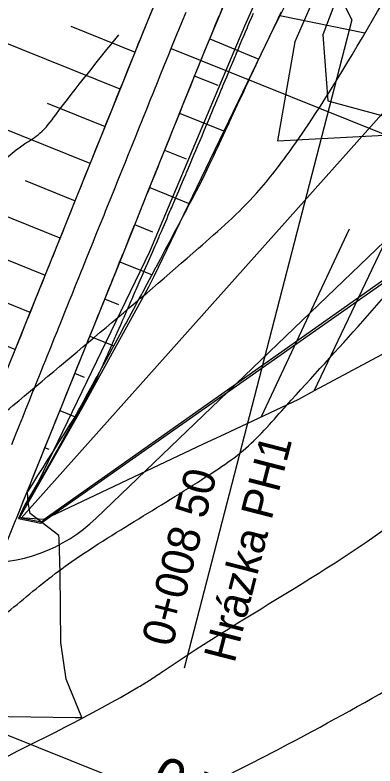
# Model space of a CAD drawing. Extents: x -564043 to -563833, y -1163561 to -1163412.
# Drawn here: x -563977.47 to -563966.25, y -1163509.03 to -1163485.61 of the extents above; entities that cross this region are included whole.
import ezdxf

# ---------------------------------------------------------------- set-up
doc = ezdxf.new("R2010")
doc.units = 0
for name, color, linetype in [('5', 7, 'Continuous'), ('_popis staničení PH1', 7, 'Continuous'), ('_popis staničení T1', 7, 'Continuous'), ('Default', 7, 'Continuous'), ('Line', 7, 'Continuous'), ('Vrstva 24', 7, 'Continuous'), ('Vrstva 25', 7, 'Continuous'), ('Vrstva 26', 7, 'Continuous')]:
    doc.layers.add(name, color=color, linetype=linetype)

msp = doc.modelspace()

# ---------------------------------------------------------------- linework, layer by layer
for points in [[(-563976.663, -1163501.462), (-563964.742, -1163493.091), (-563961.829, -1163491.15), (-563957.41, -1163486.988), (-563956.735, -1163486.627), (-563953.281, -1163481.221), (-563953.993, -1163478.343), (-563957.796, -1163470.824), (-563957.81, -1163470.439), (-563957.835, -1163469.754), (-563958.239, -1163469.063), (-563958.187, -1163468.683), (-563959.529, -1163466.077), (-563960.166, -1163464.984), (-563964.31, -1163473.527), (-563966.903, -1163478.544), (-563968.406, -1163481.669), (-563970.316, -1163485.955), (-563973.278, -1163492.988), (-563976.735, -1163500.155), (-563977.161, -1163500.889), (-563977.363, -1163501.307)], [(-563962.125, -1163475.875), (-563962.765, -1163475.108), (-563963.856, -1163475.351), (-563965.212, -1163477.785), (-563966.919, -1163483.486), (-563967.557, -1163485.407), (-563967.871, -1163486.226), (-563967.716, -1163488.285), (-563965.306, -1163488.933), (-563963.594, -1163489.868), (-563962.736, -1163489.387), (-563960.869, -1163487.453), (-563959.333, -1163482.497), (-563959.613, -1163479.666)]]:
    msp.add_lwpolyline(points, close=True)
for points in [[(-563968.084, -1163484.934), (-563968.744, -1163486.445), (-563969.289, -1163489.534), (-563965.164, -1163489.309), (-563965.164, -1163489.309), (-563964.25, -1163489.835), (-563963.508, -1163490.263), (-563963.061, -1163489.994), (-563962.883, -1163489.889), (-563962.657, -1163489.751), (-563960.727, -1163487.738), (-563960.348, -1163486.241), (-563960.31, -1163486.212), (-563960.154, -1163486.129), (-563958.95, -1163482.892)], [(-563951.913, -1163488.197), (-563954.263, -1163490.192), (-563956.079, -1163491.487), (-563957.379, -1163492.414), (-563960.591, -1163493.664), (-563961.319, -1163493.948), (-563961.866, -1163494.161), (-563963.182, -1163494.674), (-563968.138, -1163497.33), (-563968.634, -1163497.596), (-563970.944, -1163498.688), (-563971.597, -1163498.997), (-563976.56, -1163501.343), (-563977.332, -1163501.295), (-563976.988, -1163500.693), (-563975.559, -1163498.192), (-563975.396, -1163497.906), (-563973.296, -1163494.084), (-563973.133, -1163493.747), (-563971.654, -1163490.682), (-563969.513, -1163486.248), (-563968.702, -1163484.611)], [(-563977.812, -1163496.922), (-563977.438, -1163495.994), (-563977.065, -1163495.066), (-563976.691, -1163494.139), (-563976.318, -1163493.211), (-563975.945, -1163492.283), (-563975.571, -1163491.355), (-563975.198, -1163490.428), (-563974.825, -1163489.5), (-563974.451, -1163488.572), (-563974.078, -1163487.645), (-563973.705, -1163486.717), (-563973.527, -1163486.276), (-563973.328, -1163485.785), (-563972.941, -1163484.852)], [(-563977.421, -1163501.309), (-563977.076, -1163500.451), (-563977.017, -1163500.304), (-563976.703, -1163499.524), (-563976.33, -1163498.596), (-563975.956, -1163497.668), (-563975.583, -1163496.741), (-563975.209, -1163495.813), (-563974.836, -1163494.885), (-563974.463, -1163493.958), (-563974.089, -1163493.03), (-563973.716, -1163492.102), (-563973.343, -1163491.175), (-563972.969, -1163490.247), (-563972.596, -1163489.319), (-563972.223, -1163488.391), (-563971.849, -1163487.464), (-563971.672, -1163487.023), (-563971.476, -1163486.542), (-563971.097, -1163485.627), (-563970.817, -1163484.966)], [(-563977.823, -1163502.307), (-563977.45, -1163501.379), (-563977.421, -1163501.309), (-563977.309, -1163501.03), (-563977.309, -1163501.029), (-563977.198, -1163500.753), (-563977.087, -1163500.478), (-563977.076, -1163500.451), (-563976.976, -1163500.203), (-563976.865, -1163499.927), (-563976.755, -1163499.652), (-563976.703, -1163499.524), (-563976.644, -1163499.377), (-563976.533, -1163499.101), (-563976.422, -1163498.826), (-563976.33, -1163498.596), (-563976.311, -1163498.551), (-563976.201, -1163498.275), (-563976.09, -1163498), (-563975.979, -1163497.725), (-563975.956, -1163497.668), (-563975.868, -1163497.449), (-563975.757, -1163497.174), (-563975.646, -1163496.899), (-563975.583, -1163496.741), (-563975.536, -1163496.623), (-563975.425, -1163496.348), (-563975.314, -1163496.073), (-563975.209, -1163495.813), (-563975.203, -1163495.797), (-563975.092, -1163495.522), (-563974.982, -1163495.247), (-563974.871, -1163494.971), (-563974.836, -1163494.885), (-563974.76, -1163494.696), (-563974.649, -1163494.421), (-563974.538, -1163494.145), (-563974.463, -1163493.958), (-563974.428, -1163493.87), (-563974.317, -1163493.595), (-563974.206, -1163493.319), (-563974.095, -1163493.044), (-563974.089, -1163493.03), (-563973.984, -1163492.769), (-563973.873, -1163492.493), (-563973.763, -1163492.218), (-563973.716, -1163492.102), (-563973.652, -1163491.943), (-563973.541, -1163491.668), (-563973.43, -1163491.392), (-563973.343, -1163491.175), (-563973.319, -1163491.117), (-563973.209, -1163490.842), (-563973.098, -1163490.566), (-563972.987, -1163490.291), (-563972.969, -1163490.247), (-563972.876, -1163490.016), (-563972.765, -1163489.74), (-563972.655, -1163489.465), (-563972.596, -1163489.319), (-563972.544, -1163489.19), (-563972.433, -1163488.914), (-563972.322, -1163488.639), (-563972.223, -1163488.391), (-563972.211, -1163488.364), (-563972.101, -1163488.088), (-563971.99, -1163487.813), (-563971.879, -1163487.538), (-563971.849, -1163487.464), (-563971.768, -1163487.262), (-563971.672, -1163487.023), (-563971.657, -1163486.987), (-563971.547, -1163486.715), (-563971.476, -1163486.542), (-563971.436, -1163486.443), (-563971.324, -1163486.171), (-563971.212, -1163485.9), (-563971.098, -1163485.629), (-563971.097, -1163485.627), (-563970.984, -1163485.358)], [(-563977.571, -1163499.003), (-563977.461, -1163498.728), (-563977.35, -1163498.453), (-563977.257, -1163498.223), (-563977.239, -1163498.177), (-563977.128, -1163497.902), (-563977.017, -1163497.627), (-563976.907, -1163497.351), (-563976.884, -1163497.295), (-563976.796, -1163497.076), (-563976.685, -1163496.801), (-563976.574, -1163496.525), (-563976.511, -1163496.367), (-563976.463, -1163496.25), (-563976.353, -1163495.975), (-563976.242, -1163495.699), (-563976.137, -1163495.44), (-563976.131, -1163495.424), (-563976.02, -1163495.149), (-563975.909, -1163494.873), (-563975.798, -1163494.598), (-563975.764, -1163494.512), (-563975.688, -1163494.323), (-563975.577, -1163494.047), (-563975.466, -1163493.772), (-563975.39, -1163493.584), (-563975.355, -1163493.497), (-563975.244, -1163493.221), (-563975.134, -1163492.946), (-563975.023, -1163492.671), (-563975.017, -1163492.657), (-563974.912, -1163492.395), (-563974.801, -1163492.12), (-563974.69, -1163491.845), (-563974.644, -1163491.729), (-563974.58, -1163491.569), (-563974.469, -1163491.294), (-563974.358, -1163491.019), (-563974.27, -1163490.801), (-563974.247, -1163490.744), (-563974.136, -1163490.468), (-563974.025, -1163490.193), (-563973.915, -1163489.918), (-563973.897, -1163489.873), (-563973.804, -1163489.642), (-563973.693, -1163489.367), (-563973.582, -1163489.092), (-563973.524, -1163488.946), (-563973.471, -1163488.816), (-563973.361, -1163488.541), (-563973.25, -1163488.266), (-563973.15, -1163488.018), (-563973.139, -1163487.99), (-563973.028, -1163487.715), (-563972.917, -1163487.44), (-563972.807, -1163487.164), (-563972.777, -1163487.09), (-563972.696, -1163486.889), (-563972.599, -1163486.649), (-563972.585, -1163486.614), (-563972.474, -1163486.339), (-563972.402, -1163486.163), (-563972.361, -1163486.064), (-563972.249, -1163485.789), (-563972.135, -1163485.515)], [(-563977.502, -1163496.152), (-563977.438, -1163495.994), (-563977.391, -1163495.877), (-563977.28, -1163495.601), (-563977.169, -1163495.326), (-563977.065, -1163495.066), (-563977.059, -1163495.051), (-563976.948, -1163494.775), (-563976.837, -1163494.5), (-563976.726, -1163494.225), (-563976.691, -1163494.139), (-563976.615, -1163493.949), (-563976.505, -1163493.674), (-563976.394, -1163493.399), (-563976.318, -1163493.211), (-563976.283, -1163493.123), (-563976.172, -1163492.848), (-563976.061, -1163492.573), (-563975.95, -1163492.297), (-563975.945, -1163492.283), (-563975.84, -1163492.022), (-563975.729, -1163491.747), (-563975.618, -1163491.471), (-563975.571, -1163491.355), (-563975.507, -1163491.196), (-563975.396, -1163490.921), (-563975.286, -1163490.645), (-563975.198, -1163490.428), (-563975.175, -1163490.37), (-563975.064, -1163490.095), (-563974.953, -1163489.819), (-563974.842, -1163489.544), (-563974.825, -1163489.5), (-563974.732, -1163489.269), (-563974.621, -1163488.994), (-563974.51, -1163488.718), (-563974.451, -1163488.572), (-563974.399, -1163488.443), (-563974.288, -1163488.168), (-563974.177, -1163487.892), (-563974.078, -1163487.645), (-563974.067, -1163487.617), (-563973.956, -1163487.342), (-563973.845, -1163487.066), (-563973.734, -1163486.791), (-563973.705, -1163486.717), (-563973.623, -1163486.516), (-563973.527, -1163486.276), (-563973.512, -1163486.24), (-563973.4, -1163485.962), (-563973.328, -1163485.785), (-563973.287, -1163485.685), (-563973.173, -1163485.407)], [(-563977.077, -1163500.482), (-563977.061, -1163500.458), (-563976.914, -1163500.227), (-563976.753, -1163499.973), (-563976.591, -1163499.718), (-563976.516, -1163499.599), (-563976.429, -1163499.463), (-563976.268, -1163499.208), (-563976.107, -1163498.953), (-563975.973, -1163498.74), (-563975.946, -1163498.698), (-563975.785, -1163498.442), (-563975.625, -1163498.187), (-563975.48, -1163497.925), (-563975.451, -1163497.872), (-563975.336, -1163497.663), (-563975.193, -1163497.401), (-563975.049, -1163497.139), (-563974.967, -1163496.989), (-563974.906, -1163496.877), (-563974.763, -1163496.614), (-563974.62, -1163496.352), (-563974.485, -1163496.104), (-563974.477, -1163496.09), (-563974.335, -1163495.827), (-563974.192, -1163495.564), (-563974.05, -1163495.302), (-563974.006, -1163495.219), (-563973.909, -1163495.039), (-563973.767, -1163494.776), (-563973.625, -1163494.513), (-563973.529, -1163494.333), (-563973.484, -1163494.25), (-563973.343, -1163493.987), (-563973.202, -1163493.723), (-563973.062, -1163493.46), (-563973.055, -1163493.446), (-563972.922, -1163493.196), (-563972.782, -1163492.933), (-563972.642, -1163492.669), (-563972.583, -1163492.558), (-563972.502, -1163492.405), (-563972.363, -1163492.142), (-563972.224, -1163491.878), (-563972.114, -1163491.669), (-563972.085, -1163491.614), (-563971.946, -1163491.35), (-563971.808, -1163491.085), (-563971.669, -1163490.821), (-563971.647, -1163490.779), (-563971.537, -1163490.555), (-563971.41, -1163490.286), (-563971.283, -1163490.017), (-563971.216, -1163489.874), (-563971.157, -1163489.748), (-563971.03, -1163489.479), (-563970.904, -1163489.21), (-563970.791, -1163488.968), (-563970.778, -1163488.94), (-563970.653, -1163488.671), (-563970.527, -1163488.402), (-563970.402, -1163488.132), (-563970.368, -1163488.06), (-563970.277, -1163487.863), (-563970.168, -1163487.628), (-563970.152, -1163487.594), (-563970.03, -1163487.332), (-563969.952, -1163487.164), (-563969.908, -1163487.069), (-563969.785, -1163486.808), (-563969.662, -1163486.546), (-563969.538, -1163486.285), (-563969.537, -1163486.283), (-563969.414, -1163486.024), (-563969.289, -1163485.763), (-563969.233, -1163485.646), (-563969.164, -1163485.502)], [(-563977.077, -1163500.482), (-563977.061, -1163500.458), (-563976.914, -1163500.227), (-563976.753, -1163499.973), (-563976.591, -1163499.718), (-563976.516, -1163499.599), (-563976.429, -1163499.463), (-563976.268, -1163499.208), (-563976.107, -1163498.953), (-563975.973, -1163498.74), (-563975.946, -1163498.698), (-563975.785, -1163498.442), (-563975.625, -1163498.187), (-563975.48, -1163497.925), (-563975.451, -1163497.872), (-563975.336, -1163497.663), (-563975.193, -1163497.401), (-563975.049, -1163497.139), (-563974.967, -1163496.989), (-563974.906, -1163496.877), (-563974.763, -1163496.614), (-563974.62, -1163496.352), (-563974.485, -1163496.104), (-563974.477, -1163496.09), (-563974.335, -1163495.827), (-563974.192, -1163495.564), (-563974.05, -1163495.302), (-563974.006, -1163495.219), (-563973.909, -1163495.039), (-563973.767, -1163494.776), (-563973.625, -1163494.513), (-563973.529, -1163494.333), (-563973.484, -1163494.25), (-563973.343, -1163493.987), (-563973.202, -1163493.723), (-563973.062, -1163493.46), (-563973.055, -1163493.446), (-563972.922, -1163493.196), (-563972.782, -1163492.933), (-563972.642, -1163492.669), (-563972.583, -1163492.558), (-563972.502, -1163492.405), (-563972.363, -1163492.142), (-563972.224, -1163491.878), (-563972.114, -1163491.669), (-563972.085, -1163491.614), (-563971.946, -1163491.35), (-563971.808, -1163491.085), (-563971.669, -1163490.821), (-563971.647, -1163490.779), (-563971.537, -1163490.555), (-563971.41, -1163490.286), (-563971.283, -1163490.017), (-563971.216, -1163489.874), (-563971.157, -1163489.748), (-563971.03, -1163489.479), (-563970.904, -1163489.21), (-563970.791, -1163488.968), (-563970.778, -1163488.94), (-563970.653, -1163488.671), (-563970.527, -1163488.402), (-563970.402, -1163488.132), (-563970.368, -1163488.06), (-563970.277, -1163487.863), (-563970.168, -1163487.628), (-563970.152, -1163487.594), (-563970.03, -1163487.332), (-563969.952, -1163487.164), (-563969.908, -1163487.069), (-563969.785, -1163486.808), (-563969.662, -1163486.546), (-563969.538, -1163486.285), (-563969.537, -1163486.283), (-563969.414, -1163486.024), (-563969.289, -1163485.763), (-563969.233, -1163485.646), (-563969.164, -1163485.502)], [(-563979.198, -1163507.467), (-563978.368, -1163507.477), (-563975.597, -1163507.515), (-563975.386, -1163507.517), (-563975.87, -1163506.327), (-563976.036, -1163505.182), (-563976.046, -1163504.1), (-563976.056, -1163503.018), (-563976.088, -1163501.927), (-563976.1, -1163501.84), (-563976.996, -1163501.156), (-563976.997, -1163501.154), (-563977.062, -1163500.808), (-563977.077, -1163500.482)], [(-563979.198, -1163507.467), (-563978.368, -1163507.477), (-563975.597, -1163507.515), (-563975.386, -1163507.517), (-563975.87, -1163506.327), (-563976.036, -1163505.182), (-563976.046, -1163504.1), (-563976.056, -1163503.018), (-563976.088, -1163501.927), (-563976.1, -1163501.84), (-563976.996, -1163501.156), (-563976.997, -1163501.154), (-563977.062, -1163500.808), (-563977.077, -1163500.482)]]:
    msp.add_lwpolyline(points)
at = {"layer": '5'}
msp.add_line((-563974.94, -1163501.303), (-563959.546, -1163486.507), dxfattribs=at)
msp.add_arc((-563978.405, -1163497.698), 5, 218.997, 313.8653, dxfattribs=at)
at = {"layer": '_popis staničení PH1'}
for points in [[(-563972.599, -1163486.649), (-563954.098, -1163494.096)], [(-563980.73, -1163506.85), (-563966.814, -1163512.451)]]:
    msp.add_lwpolyline(points, dxfattribs=at)
at = {"layer": '_popis staničení T1'}
msp.add_lwpolyline([(-563969.764, -1163480.269), (-563966.967, -1163485.757), (-563972.194, -1163505.976)], dxfattribs=at)
at = {"layer": 'Default'}
msp.add_lwpolyline([(-563962.482, -1163491.404), (-563976.56, -1163501.343), (-563976.657, -1163501.429), (-563977.332, -1163501.295), (-563974.976, -1163497.082), (-563974.974, -1163497.079), (-563974.939, -1163497), (-563974.935, -1163496.992), (-563974.849, -1163496.797), (-563974.841, -1163496.78), (-563974.722, -1163496.513), (-563974.711, -1163496.488), (-563974.596, -1163496.229), (-563974.589, -1163496.212), (-563974.532, -1163496.085), (-563974.525, -1163496.068), (-563974.47, -1163495.944), (-563974.453, -1163495.906), (-563974.344, -1163495.659), (-563974.324, -1163495.615), (-563974.218, -1163495.374), (-563974.203, -1163495.339), (-563974.128, -1163495.17), (-563974.122, -1163495.155), (-563974.093, -1163495.09), (-563974.069, -1163495.034), (-563973.968, -1163494.805), (-563973.941, -1163494.744), (-563973.843, -1163494.52), (-563973.816, -1163494.459), (-563973.727, -1163494.254), (-563973.725, -1163494.249), (-563973.718, -1163494.234), (-563973.688, -1163494.165), (-563973.594, -1163493.949), (-563973.562, -1163493.876), (-563973.47, -1163493.664), (-563973.436, -1163493.586), (-563973.346, -1163493.378), (-563973.341, -1163493.366), (-563973.328, -1163493.337), (-563973.297, -1163493.267), (-563973.222, -1163493.093), (-563973.185, -1163493.008), (-563973.099, -1163492.807), (-563973.061, -1163492.719), (-563972.975, -1163492.522), (-563972.961, -1163492.488), (-563972.931, -1163492.418), (-563972.905, -1163492.359), (-563972.852, -1163492.236), (-563972.812, -1163492.141), (-563972.729, -1163491.95), (-563972.688, -1163491.852), (-563972.607, -1163491.664), (-563972.582, -1163491.606), (-563972.536, -1163491.499), (-563972.518, -1163491.456), (-563972.485, -1163491.378), (-563972.441, -1163491.275), (-563972.363, -1163491.092), (-563972.318, -1163490.986), (-563972.241, -1163490.805), (-563972.204, -1163490.719), (-563972.145, -1163490.579), (-563972.135, -1163490.556), (-563972.119, -1163490.519), (-563972.072, -1163490.408), (-563971.998, -1163490.232), (-563971.95, -1163490.12), (-563971.877, -1163489.946), (-563971.829, -1163489.833), (-563971.756, -1163489.659), (-563971.756, -1163489.659), (-563971.755, -1163489.658), (-563971.707, -1163489.544), (-563971.635, -1163489.372), (-563971.587, -1163489.257), (-563971.515, -1163489.086), (-563971.466, -1163488.969), (-563971.395, -1163488.799), (-563971.384, -1163488.773), (-563971.368, -1163488.735), (-563971.33, -1163488.644), (-563971.275, -1163488.512), (-563971.225, -1163488.393), (-563971.155, -1163488.224), (-563971.105, -1163488.105), (-563971.036, -1163487.937), (-563971.014, -1163487.885), (-563970.984, -1163487.812), (-563970.955, -1163487.744), (-563970.916, -1163487.65), (-563970.868, -1163487.533), (-563970.802, -1163487.373), (-563970.8, -1163487.368), (-563970.797, -1163487.363), (-563970.747, -1163487.242), (-563970.68, -1163487.081), (-563970.647, -1163487.002), (-563970.604, -1163486.898), (-563970.586, -1163486.855), (-563970.563, -1163486.799), (-563970.511, -1163486.677), (-563970.445, -1163486.518), (-563970.392, -1163486.395), (-563970.326, -1163486.237), (-563970.28, -1163486.13), (-563970.222, -1163485.995), (-563970.215, -1163485.978), (-563970.206, -1163485.957), (-563970.153, -1163485.832), (-563970.086, -1163485.676), (-563970.032, -1163485.551)], dxfattribs=at)
at = {"layer": 'Line'}
for p, q in [((-563962.901, -1163485.181), (-563977.279, -1163501.298)), ((-563966.564, -1163486.174), (-563969.208, -1163485.632)), ((-563975.726, -1163485.954), (-563973.723, -1163486.764)), ((-563968.138, -1163497.33), (-563962.69, -1163485.858)), ((-563974.19, -1163487.923), (-563977.994, -1163486.392)), ((-563971.398, -1163486.352), (-563969.867, -1163486.983)), ((-563971.129, -1163487.809), (-563971.868, -1163487.51)), ((-563976.466, -1163488.355), (-563974.657, -1163489.083)), ((-563975.123, -1163490.242), (-563978.542, -1163488.867)), ((-563972.335, -1163488.67), (-563970.918, -1163489.24)), ((-563972.126, -1163490.101), (-563972.801, -1163489.829)), ((-563977.155, -1163490.772), (-563975.59, -1163491.402)), ((-563973.268, -1163490.989), (-563972.021, -1163491.491)), ((-563976.057, -1163492.562), (-563978.885, -1163491.423)), ((-563973.171, -1163492.376), (-563973.735, -1163492.149)), ((-563967.053, -1163492.285), (-563969.789, -1163498.142)), ((-563977.783, -1163493.214), (-563976.523, -1163493.721)), ((-563974.201, -1163493.308), (-563973.196, -1163493.713)), ((-563976.99, -1163494.881), (-563979.193, -1163493.994)), ((-563974.23, -1163494.644), (-563974.668, -1163494.468)), ((-563978.396, -1163495.662), (-563977.457, -1163496.04)), ((-563975.135, -1163495.627), (-563974.389, -1163495.928)), ((-563975.296, -1163496.91), (-563975.602, -1163496.787)), ((-563976.068, -1163497.947), (-563975.597, -1163498.136)), ((-563976.403, -1163499.159), (-563976.535, -1163499.106)), ((-563977.002, -1163500.266), (-563976.952, -1163500.286))]:
    msp.add_line(p, q, dxfattribs=at)
at = {"layer": 'Vrstva 24'}
for points in [[(-563987.107, -1163486.915), (-563987.454, -1163489.613), (-563987.517, -1163490.15), (-563987.54, -1163490.422), (-563987.53, -1163490.559), (-563987.493, -1163490.695), (-563987.417, -1163490.784), (-563987.298, -1163490.832), (-563987.065, -1163490.801), (-563986.897, -1163490.636), (-563986.866, -1163490.616), (-563986.653, -1163490.561), (-563986.65, -1163490.24), (-563986.645, -1163490.2), (-563986.382, -1163489.381), (-563986.092, -1163488.576), (-563985.799, -1163487.775), (-563985.528, -1163486.967), (-563985.38, -1163486.476), (-563984.961, -1163484.997), (-563984.678, -1163484.011), (-563984.372, -1163483.032), (-563984.225, -1163482.649), (-563983.962, -1163482.075), (-563983.672, -1163481.512), (-563983.189, -1163480.348), (-563983.119, -1163479.959), (-563982.881, -1163478.598), (-563982.738, -1163477.921), (-563982.65, -1163477.583), (-563982.6, -1163477.415), (-563982.546, -1163477.247), (-563982.332, -1163477.109), (-563982.215, -1163477.074), (-563982.092, -1163477.059), (-563981.971, -1163477.035), (-563981.858, -1163476.974), (-563981.222, -1163476.317), (-563980.763, -1163475.576), (-563980.303, -1163473.933), (-563980.283, -1163473.505), (-563980.299, -1163473.076), (-563980.318, -1163472.648), (-563980.308, -1163472.221), (-563980.208, -1163471.241), (-563979.978, -1163470.27), (-563979.506, -1163469.655), (-563979.053, -1163469.383), (-563978.331, -1163469.068), (-563977.756, -1163469.029), (-563977.053, -1163469.053), (-563976.495, -1163468.977), (-563976.227, -1163468.861), (-563976.095, -1163468.775), (-563975.963, -1163468.666), (-563975.645, -1163468.239), (-563975.569, -1163468.015), (-563975.54, -1163467.788), (-563975.712, -1163467.263), (-563975.92, -1163467.014), (-563976.134, -1163466.799), (-563976.603, -1163466.431), (-563977.767, -1163465.694), (-563978.114, -1163465.416), (-563978.319, -1163465.046), (-563978.354, -1163464.593), (-563978.366, -1163464.139), (-563978.374, -1163463.685), (-563978.396, -1163463.232), (-563978.403, -1163463.165), (-563978.508, -1163462.771), (-563978.665, -1163462.394), (-563979.088, -1163461.691), (-563979.473, -1163461.171), (-563980.119, -1163460.346)], [(-563978.297, -1163509.021), (-563978.261, -1163509.003), (-563973.613, -1163506.565), (-563973.263, -1163506.351), (-563972.852, -1163506.074), (-563964.784, -1163500.778), (-563963.064, -1163499.262), (-563960.133, -1163495.845), (-563958.857, -1163494.133), (-563956.661, -1163490.461), (-563954.703, -1163486.917), (-563951.017, -1163480.396), (-563950.659, -1163479.782), (-563950.563, -1163479.619)], [(-563978.949, -1163516.619), (-563975.171, -1163515.313), (-563974.108, -1163514.884), (-563972.002, -1163513.885), (-563969.907, -1163512.865), (-563967.813, -1163511.846), (-563965.709, -1163510.847), (-563964.325, -1163510.207), (-563962.597, -1163509.381), (-563961.075, -1163508.613), (-563959.57, -1163507.812), (-563958.075, -1163506.99), (-563956.583, -1163506.159), (-563955.558, -1163505.578), (-563954.547, -1163504.976), (-563953.555, -1163504.342), (-563952.588, -1163503.665), (-563951.319, -1163502.66), (-563950.112, -1163501.587), (-563949.038, -1163500.583), (-563947.98, -1163499.563), (-563946.918, -1163498.547), (-563945.835, -1163497.554), (-563945.703, -1163497.443), (-563945.609, -1163497.371), (-563945.171, -1163496.955), (-563943.72, -1163495.5)]]:
    msp.add_spline(points, degree=3, dxfattribs=at)
at = {"layer": 'Vrstva 25'}
msp.add_spline([(-563979.181, -1163499.008), (-563978.428, -1163498.506), (-563977.533, -1163497.79), (-563971.745, -1163492.882), (-563969.933, -1163491.157), (-563968.824, -1163489.747), (-563966.163, -1163485.494), (-563965.399, -1163484.181), (-563964.1, -1163481.868), (-563961.431, -1163477.021), (-563960.731, -1163475.725), (-563960.044, -1163474.189), (-563959.617, -1163472.641), (-563959.116, -1163469.866), (-563959.228, -1163469.046), (-563959.512, -1163468.326), (-563959.82, -1163467.638), (-563960.515, -1163466.313), (-563961.208, -1163465.1)], degree=3, dxfattribs=at)
at = {"layer": 'Vrstva 26'}
for points in [[(-563980.746, -1163506.255), (-563980.047, -1163505.928), (-563978.898, -1163505.186), (-563978.091, -1163504.559), (-563977.304, -1163503.908), (-563976.514, -1163503.264), (-563975.695, -1163502.656), (-563974.591, -1163501.929), (-563973.468, -1163501.232), (-563972.341, -1163500.538), (-563971.226, -1163499.825), (-563970.447, -1163499.268), (-563969.15, -1163497.951), (-563964.517, -1163492.611), (-563963.2, -1163490.7), (-563960.284, -1163485.41), (-563958.779, -1163482.786), (-563956.142, -1163478.307), (-563954.428, -1163475.228)], [(-564001.195, -1163498.271), (-563999.625, -1163497.54), (-563999.32, -1163497.49), (-563999.014, -1163497.455), (-563998.404, -1163497.374), (-563997.456, -1163497.19), (-563996.983, -1163497.106), (-563996.746, -1163497.08), (-563996.628, -1163497.073), (-563996.51, -1163497.07), (-563996.001, -1163497.405), (-563995.843, -1163497.69), (-563995.811, -1163497.929), (-563995.865, -1163498.008), (-563995.966, -1163498.084), (-563996.177, -1163498.245), (-563996.314, -1163498.396), (-563996.473, -1163498.559), (-563996.786, -1163498.911), (-563996.954, -1163499.618), (-563996.725, -1163499.926), (-563996.435, -1163500.208), (-563996.113, -1163500.428), (-563995.791, -1163500.55), (-563995.579, -1163500.527), (-563995.362, -1163500.405), (-563995.147, -1163500.225), (-563994.94, -1163500.032), (-563994.454, -1163499.316), (-563994.189, -1163498.497), (-563993.911, -1163497.703), (-563993.694, -1163497.356), (-563993.385, -1163497.063), (-563993.106, -1163496.925), (-563992.801, -1163496.863), (-563992.211, -1163496.877), (-563991.901, -1163497.039), (-563991.591, -1163497.33), (-563991.287, -1163497.564), (-563990.995, -1163497.556), (-563990.269, -1163497.037), (-563989.554, -1163496.504), (-563988.84, -1163495.969), (-563988.119, -1163495.444), (-563987.86, -1163495.24), (-563987.725, -1163495.146), (-563987.573, -1163495.071), (-563987.369, -1163495.063), (-563987.165, -1163495.092), (-563986.561, -1163495.087), (-563985.951, -1163495.108), (-563984.727, -1163495.135), (-563983.531, -1163494.982), (-563982.954, -1163494.778), (-563982.673, -1163494.634), (-563982.398, -1163494.458), (-563981.989, -1163494.127), (-563981.638, -1163493.78), (-563980.962, -1163493.086), (-563979.072, -1163491.35), (-563977.168, -1163489.628), (-563976.69, -1163489.292), (-563976.196, -1163488.717), (-563974.229, -1163486.225)], [(-563979.339, -1163513.451), (-563976.454, -1163512.115), (-563974.079, -1163510.944), (-563968.189, -1163507.943), (-563964.488, -1163505.88), (-563958.479, -1163502.145), (-563957, -1163500.857), (-563954.437, -1163497.718), (-563953.277, -1163496.363), (-563952.789, -1163495.73), (-563951.998, -1163494.583), (-563951.243, -1163493.409), (-563950.48, -1163492.242), (-563949.665, -1163491.113), (-563947.525, -1163488.408), (-563947.448, -1163488.312)], [(-563978.978, -1163519.771), (-563978.765, -1163519.704), (-563976.028, -1163518.79), (-563972.649, -1163517.594), (-563970.971, -1163516.964), (-563969.305, -1163516.304), (-563967.032, -1163515.3), (-563965.961, -1163514.798), (-563964.896, -1163514.286), (-563963.829, -1163513.774), (-563962.756, -1163513.276), (-563957.668, -1163511.196), (-563957.314, -1163511.075), (-563956.846, -1163510.894), (-563954.728, -1163509.895), (-563952.637, -1163508.844), (-563950.551, -1163507.783), (-563948.449, -1163506.755), (-563947.233, -1163506.198), (-563945.851, -1163505.471), (-563944.971, -1163504.882), (-563944.101, -1163504.279), (-563942.358, -1163503.079), (-563941.411, -1163502.449)]]:
    msp.add_spline(points, degree=3, dxfattribs=at)

# ---------------------------------------------------------------- texts
at = {"layer": '_popis staničení PH1'}
msp.add_text('0+004.70', height=1.25, rotation=158.0764, dxfattribs=at).set_placement((-563966.348, -1163511.291))
at = {"layer": '_popis staničení T1'}
for s, p in [('Hrázka PH1', (-563970.628, -1163505.853)), ('0+008 50 ', (-563972.567, -1163505.352))]:
    msp.add_text(s, height=1, rotation=75.5058, dxfattribs=at).set_placement(p)

doc.saveas('drawing.dxf')
